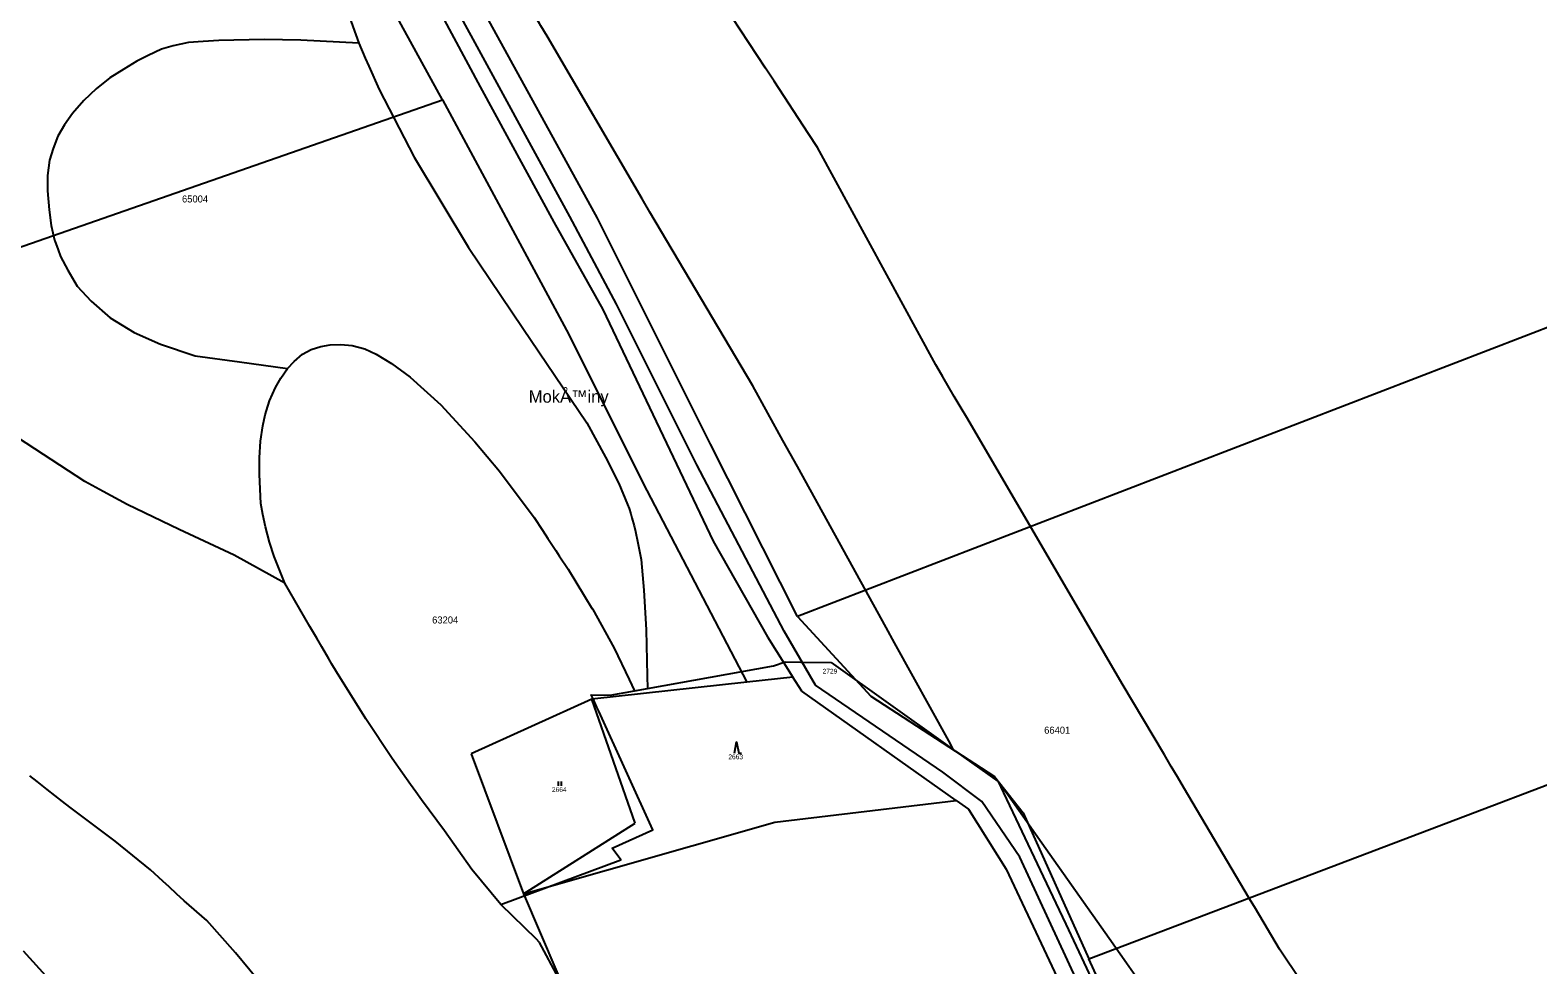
# Model space of a CAD drawing. Extents: x -546762 to -540209, y -1046851 to -1035694.
# Drawn here: x -541709 to -541172, y -1039160 to -1038827 of the extents above; entities that cross this region are included whole.
import ezdxf

# ---------------------------------------------------------------- set-up
doc = ezdxf.new("R2010")
doc.units = 0
for name, color, linetype in [('Vrstva 1', 7, 'Continuous'), ('Vrstva 15', 7, 'Continuous'), ('Vrstva 18', 7, 'Continuous'), ('Vrstva 25', 7, 'Continuous'), ('Vrstva 52', 7, 'Continuous'), ('Vrstva 53', 7, 'Continuous')]:
    doc.layers.add(name, color=color, linetype=linetype)

msp = doc.modelspace()

# ---------------------------------------------------------------- linework, layer by layer
at = {"layer": 'Vrstva 1'}
for points in [[(-541543.25, -1038844.31), (-541578.01, -1038780.71)], [(-541506.89, -1038893.6), (-541568.56, -1038781.24)], [(-541581.9, -1038784.9), (-541548.61, -1038846.92)], [(-541562.11, -1038851.5), (-541595.51, -1038790.38)], [(-541548.61, -1038846.92), (-541522.46, -1038895.1)], [(-541516.68, -1038893.11), (-541543.25, -1038844.31)], [(-541729.29, -1038909.8), (-541562.11, -1038851.5)], [(-541562.11, -1038851.5), (-541517.85, -1038933.49)], [(-541522.46, -1038895.1), (-541504.94, -1038926.2)], [(-541500.08, -1038924.32), (-541516.68, -1038893.11)], [(-541466.61, -1038974.1), (-541506.89, -1038893.6)], [(-541504.94, -1038926.2), (-541465.68, -1039008.66)], [(-541471.5, -1038981.55), (-541500.08, -1038924.32)], [(-541150.97, -1038925.82), (-541293.31, -1038980.69)], [(-541517.85, -1038933.49), (-541489.3, -1038990.68)], [(-541435.65, -1039035.56), (-541466.61, -1038974.1)], [(-541440.39, -1039040.67), (-541471.5, -1038981.55)], [(-541293.31, -1038980.69), (-541435.65, -1039035.56)], [(-541489.3, -1038990.68), (-541453.67, -1039058.87)], [(-541465.68, -1039008.66), (-541446.29, -1039042.74)], [(-541435.65, -1039035.56), (-541409.49, -1039063.9)], [(-541429.18, -1039060.01), (-541440.39, -1039040.67)], [(-541446.29, -1039042.74), (-541437.28, -1039057.08)], [(-541188.34, -1039102.87), (-541044.82, -1039048.38)], [(-541437.28, -1039057.08), (-541453.67, -1039058.87)], [(-541434.14, -1039062.06), (-541437.28, -1039057.08)], [(-541453.67, -1039058.87), (-541508.83, -1039064.94)], [(-541379.1, -1039101.08), (-541434.14, -1039062.06)], [(-541383.92, -1039090.88), (-541429.18, -1039060.01)], [(-541508.83, -1039064.94), (-541551.84, -1039084.41)], [(-541493.4, -1039109.04), (-541508.83, -1039064.94)], [(-541409.49, -1039063.9), (-541365.47, -1039092.51)], [(-541551.84, -1039084.41), (-541533.2, -1039134.23)], [(-541370.02, -1039101.39), (-541383.92, -1039090.88)], [(-541365.47, -1039092.51), (-541355.24, -1039105.41)], [(-541443.73, -1039108.71), (-541379.1, -1039101.08)], [(-541379.1, -1039101.08), (-541374.79, -1039104.13)], [(-541374.79, -1039104.13), (-541361.29, -1039125.46)], [(-541356.44, -1039121.16), (-541370.02, -1039101.39)], [(-541355.24, -1039105.41), (-541331.86, -1039157.35)], [(-541331.86, -1039157.35), (-541188.34, -1039102.87)], [(-541533.2, -1039134.23), (-541443.73, -1039108.71)], [(-541533.2, -1039134.23), (-541493.4, -1039109.04)], [(-541298.92, -1039245.54), (-541356.44, -1039121.16)], [(-541361.29, -1039125.46), (-541316.4, -1039220.98)], [(-541533.2, -1039134.23), (-541490.9, -1039233.13)], [(-541326.82, -1039168.53), (-541331.86, -1039157.35)]]:
    msp.add_lwpolyline(points, dxfattribs=at)
at = {"layer": 'Vrstva 25'}
for p, q in [((-541520.71, -1039095.79), (-541520.71, -1039094.29)), ((-541519.71, -1039095.79), (-541519.71, -1039094.29))]:
    msp.add_line(p, q, dxfattribs=at)
msp.add_lwpolyline([(-541458.07, -1039084.12), (-541457.37, -1039080.12), (-541456.57, -1039084.12), (-541455.57, -1039084.12)], dxfattribs=at)
at = {"layer": 'Vrstva 52'}
for points in [[(-541380.04, -1039082.96), (-541381.79, -1039079.78), (-541401.05, -1039044.89), (-541404.1, -1039039.37), (-541435.69, -1038982.14), (-541438.3, -1038977.41), (-541440.84, -1038972.81), (-541451.59, -1038953.35), (-541488.19, -1038891.57), (-541490.98, -1038886.8), (-541524.83, -1038828.9), (-541527.04, -1038825.13), (-541527.53, -1038824.28), (-541564.9, -1038761.93), (-541566.67, -1038758.97), (-541568.59, -1038755.36), (-541581.53, -1038730.99), (-541583.02, -1038728.19), (-541586.54, -1038721.57), (-541599.08, -1038699.34), (-541612.42, -1038677.5)], [(-541598.43, -1038813.06), (-541591.9, -1038831.36)], [(-541224.75, -1039212.6), (-541263.98, -1039153.96), (-541272.55, -1039139.51), (-541274.64, -1039135.98), (-541298.19, -1039096.26), (-541300.36, -1039092.6), (-541302.53, -1039088.94), (-541305.01, -1039084.76), (-541320.02, -1039059.45), (-541339.76, -1039025.67), (-541375.39, -1038964.68), (-541377.38, -1038961.27), (-541379.81, -1038957.11), (-541383.84, -1038950.21), (-541386.04, -1038946.44), (-541386.4, -1038945.83), (-541428.49, -1038868.48), (-541431.68, -1038863.62), (-541443.98, -1038844.91), (-541447.04, -1038840.25), (-541461.88, -1038817.68)], [(-541591.9, -1038831.36), (-541612.46, -1038830.28), (-541625.53, -1038830.01), (-541641.66, -1038830.39), (-541647.33, -1038830.69), (-541652.56, -1038831.14), (-541657.94, -1038832.33), (-541662.12, -1038833.53), (-541666.9, -1038835.77), (-541670.93, -1038837.71), (-541675.56, -1038840.55), (-541680.49, -1038843.69), (-541685.42, -1038847.57), (-541689.75, -1038851.76), (-541693.79, -1038856.39), (-541696.62, -1038860.43), (-541699.01, -1038864.46), (-541700.66, -1038868.8), (-541702, -1038872.98), (-541702.75, -1038878.51), (-541702.75, -1038883.89), (-541702.15, -1038890.69), (-541701.4, -1038896.22), (-541700.21, -1038901.45), (-541700.1, -1038901.75), (-541698.95, -1038904.95), (-541698.12, -1038907.28), (-541695.43, -1038912.21), (-541692.14, -1038917.89), (-541687.21, -1038923.27), (-541680.34, -1038929.1), (-541671.83, -1038934.33), (-541662.42, -1038938.51), (-541650.17, -1038942.7), (-541634.34, -1038944.79), (-541617.3, -1038947.16)], [(-541591.9, -1038831.36), (-541589.55, -1038836.65), (-541588.25, -1038839.58), (-541584.58, -1038847.84), (-541572.13, -1038871.92), (-541552.79, -1038904.09), (-541545.2, -1038915.37), (-541533.44, -1038932.86)], [(-541618.18, -1039023.63), (-541636.21, -1039013.69), (-541655.82, -1039004.54), (-541674.38, -1038995.64), (-541682.91, -1038991.02), (-541689.47, -1038987.47), (-541716.14, -1038969.95), (-541734.69, -1038955.3), (-541752.21, -1038940.39), (-541765.14, -1038928), (-541768.25, -1038925.02), (-541770.77, -1038922.61), (-541787.76, -1038902.73), (-541788.67, -1038901.71), (-541802.88, -1038885.77), (-541810.95, -1038873.67), (-541816.47, -1038864.4), (-541820.06, -1038856.78)], [(-541533.44, -1038932.86), (-541510.7, -1038966.59), (-541504.06, -1038978.77), (-541499.28, -1038988.19), (-541496.13, -1038995.64), (-541495.55, -1038997.01), (-541495.02, -1038998.96), (-541494.63, -1039000.38), (-541493.85, -1039003.25), (-541493.31, -1039005.23), (-541492.54, -1039009.23), (-541491.37, -1039015.24), (-541490.32, -1039026.15), (-541489.58, -1039040.2), (-541489.2, -1039056.68), (-541489.1, -1039061.14)], [(-541617.3, -1038947.16), (-541614.91, -1038944.68), (-541611.92, -1038942.12), (-541608.85, -1038940.41), (-541605.43, -1038939.3), (-541602.02, -1038938.71), (-541598.26, -1038938.62), (-541594.25, -1038939.05), (-541589.73, -1038940.16), (-541587.71, -1038941.09), (-541585.63, -1038942.04), (-541580.17, -1038945.37), (-541573.6, -1038950.32), (-541562.67, -1038960.14), (-541550.52, -1038973.34), (-541541.71, -1038983.8), (-541529.46, -1039000.24), (-541526.46, -1039004.8), (-541524.52, -1039007.74), (-541521.72, -1039012), (-541520.49, -1039013.87), (-541517.36, -1039018.62), (-541511.5, -1039028.21), (-541508.74, -1039032.74), (-541508.69, -1039032.82), (-541500.93, -1039046.72), (-541495.59, -1039057.92), (-541493.66, -1039061.96)], [(-541618.18, -1039023.63), (-541622.01, -1039014.16), (-541623.66, -1039009.08), (-541625.06, -1039003.59), (-541626, -1038999.15), (-541626.69, -1038995.22), (-541627.03, -1038990.1), (-541627.28, -1038984.8), (-541627.2, -1038978.99), (-541626.86, -1038973.02), (-541626.09, -1038967.55), (-541625.23, -1038963.64), (-541624.73, -1038962.1), (-541623.61, -1038958.69), (-541621.56, -1038953.91), (-541619.6, -1038950.66), (-541617.3, -1038947.16)], [(-541541.26, -1039138), (-541551.62, -1039125.55), (-541561.33, -1039111.8), (-541569.54, -1039100.74), (-541571.53, -1039097.95), (-541573.41, -1039095.31), (-541576.26, -1039091.29), (-541579.96, -1039086.09), (-541589.37, -1039071.97), (-541599.83, -1039055.23), (-541601.42, -1039052.49), (-541602.56, -1039050.53), (-541605.02, -1039046.29), (-541606.77, -1039043.27), (-541609.24, -1039039.02), (-541618.18, -1039023.63)], [(-541489.1, -1039061.14), (-541444.15, -1039053.04), (-541440, -1039051.62), (-541434.44, -1039051.73), (-541423.66, -1039051.94)], [(-541423.66, -1039051.94), (-541383.04, -1039080.83), (-541380.04, -1039082.96)], [(-541541.26, -1039138), (-541498.56, -1039122.21), (-541501.66, -1039118.05), (-541487.16, -1039111.43), (-541506.42, -1039069.22), (-541507.05, -1039067.84), (-541508.34, -1039065.03), (-541509.11, -1039063.35), (-541502.35, -1039063.53), (-541493.66, -1039061.96)], [(-541493.66, -1039061.96), (-541489.1, -1039061.14)], [(-541380.04, -1039082.96), (-541364.17, -1039094.25)], [(-541625.53, -1039167.56), (-541635.72, -1039155.27), (-541645.92, -1039143.76), (-541654.02, -1039136.7), (-541656.76, -1039134.2), (-541659.44, -1039131.75), (-541661.63, -1039129.75), (-541666.05, -1039125.72), (-541678.59, -1039115.52), (-541694.81, -1039103.34), (-541697.41, -1039101.39), (-541702.84, -1039097.12), (-541706.43, -1039094.3), (-541709.02, -1039092.27)], [(-541364.17, -1039094.25), (-541362.24, -1039098.34), (-541349.25, -1039125.81), (-541343.67, -1039137.6), (-541340.15, -1039145.06), (-541332.77, -1039160.68), (-541331.18, -1039164.03), (-541304.84, -1039219.76), (-541313.64, -1039219.14), (-541315.92, -1039218.98), (-541332.77, -1039217.83), (-541335.04, -1039217.69)], [(-541271.96, -1039217.53), (-541275.86, -1039213.87), (-541292.59, -1039194.78), (-541305.4, -1039179.09), (-541312.58, -1039167.5), (-541313.51, -1039166.01), (-541318.52, -1039158.92), (-541320.73, -1039155.78), (-541324.68, -1039150.19), (-541348.63, -1039116.27), (-541361.38, -1039098.2), (-541364.17, -1039094.25)], [(-541491.51, -1039231.4), (-541493.71, -1039229.4), (-541492.73, -1039229.04), (-541495.98, -1039220.01), (-541503.95, -1039197.87), (-541504.72, -1039195.73), (-541506.33, -1039191.24), (-541508.19, -1039187.74), (-541514.01, -1039176.75), (-541527.51, -1039151.61), (-541527.59, -1039151.46), (-541528.62, -1039150.45), (-541541.26, -1039138)], [(-541711.41, -1039154.59), (-541699.95, -1039167.17), (-541687.4, -1039182.6), (-541678.28, -1039195.81), (-541675.12, -1039200.38), (-541662.05, -1039219.73), (-541645.06, -1039248.24), (-541631.47, -1039272.57), (-541623.2, -1039290.46), (-541618.66, -1039300.29), (-541613.96, -1039308.4), (-541609.48, -1039316.02), (-541603.95, -1039324.84), (-541596.04, -1039335), (-541586.78, -1039346.21), (-541577.37, -1039357.42), (-541574.04, -1039361.27), (-541568.7, -1039367.43), (-541558.99, -1039377.6), (-541555.58, -1039380.37)]]:
    msp.add_lwpolyline(points, dxfattribs=at)

# ---------------------------------------------------------------- texts
at = {"layer": 'Vrstva 15'}
msp.add_text('MokÅ™iny', height=4.4, dxfattribs=at).set_placement((-541531.33, -1038959.36))
at = {"layer": 'Vrstva 18'}
for s, p in [('2729', (-541426.69, -1039055.83)), ('2663', (-541460.26, -1039086.33)), ('2664', (-541523.1, -1039098))]:
    msp.add_text(s, height=1.7, dxfattribs=at).set_placement(p)
at = {"layer": 'Vrstva 53'}
for s, p in [('65004', (-541654.82, -1038888.07)), ('63204', (-541565.75, -1039037.99)), ('66401', (-541347.81, -1039077.23))]:
    msp.add_text(s, height=2.5, dxfattribs=at).set_placement(p)

doc.saveas('drawing.dxf')
